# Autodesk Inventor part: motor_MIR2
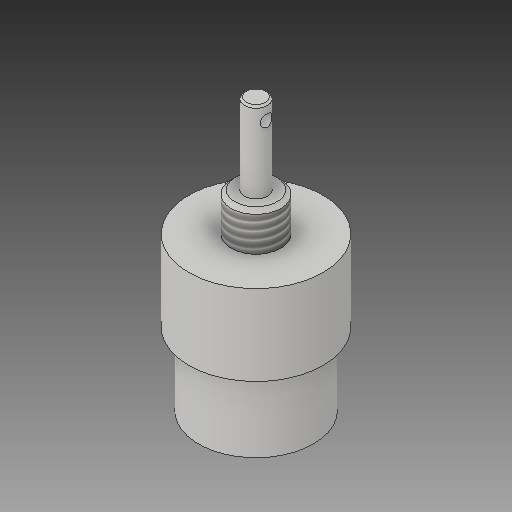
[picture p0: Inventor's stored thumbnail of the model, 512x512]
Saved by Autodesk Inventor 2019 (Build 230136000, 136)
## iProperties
Created: 2019-10
Part Number: motor_MIR2
Material: Generic
Document SubType Name: Modeling
Designer: Sangeetha Jathar
Density: 1 g/cm^3
Appearance: Default
Author: Asus
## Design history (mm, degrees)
derived "motor.ipt"
  sketch "Sketch1"
    geometry: C1 r 6.5 at (0, 0) reference; 1 further point
  sketch "Sketch2"
    geometry: 1 further point
  sketch "Sketch3"
    geometry: C1 r 17.5 at (0, 0) reference; 1 further point
  sketch "Sketch4"
    geometry: C1 r 15 at (0, 0) reference; 1 further point
  sketch "Sketch5"
    geometry: C1 r 3 at (0, 0) reference; 1 further point
  sketch "Sketch6"
    geometry: C1 r 1.55 at (-27.143, 0) reference; 1 further point
  sketch "Sketch7"
    geometry: L1 (-12.192, 2.12)-(-11.485, 2.12) reference; L2 (-11.485, 2.12)-(-11.485, -2.356) reference; L3 (-11.485, -2.356)-(-12.192, -2.356) reference; L4 (-12.192, -2.356)-(-12.192, 2.12) reference; L5 (11.603, 2.12)-(12.546, 2.12) reference; L6 (12.546, 2.12)-(12.546, -2.356) reference; L7 (12.546, -2.356)-(11.603, -2.356) reference; L8 (11.603, -2.356)-(11.603, 2.12) reference; 1 further point
feature "Solid1::motor.ipt"
tag "TaggingFeature1"
body "Solid1"
